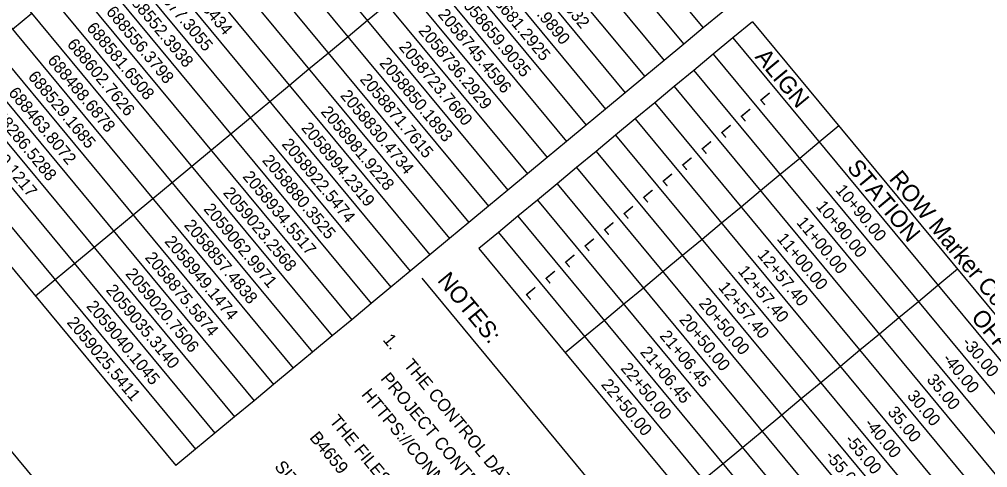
# Model space of a CAD drawing. Extents: x 2057130 to 2060012, y 687175 to 689912.
# Drawn here: x 2058231 to 2058941, y 687802 to 688130 of the extents above; entities that cross this region are included whole.
import ezdxf

# ---------------------------------------------------------------- set-up
doc = ezdxf.new("R2010")
doc.units = 0
for name, color, linetype in [('CTL Sheet Border CELL', 7, 'Continuous'), ('CTL Sheet Notes CELL', 7, 'Continuous'), ('CTL Sheet Table Cell', 7, 'Continuous'), ('CTL Sheet Text', 7, 'Continuous')]:
    doc.layers.add(name, color=color, linetype=linetype)

msp = doc.modelspace()

# ---------------------------------------------------------------- linework, layer by layer
at = {"layer": 'CTL Sheet Border CELL'}
msp.add_lwpolyline([(2059967.32, 688179.94), (2058531.08, 689911.91), (2057318.71, 688906.55), (2058754.95, 687174.58)], close=True, dxfattribs=at)
at = {"layer": 'CTL Sheet Notes CELL'}
msp.add_line((2058526.13, 687940.24), (2058938.91, 687442.47), dxfattribs=at)
at = {"layer": 'CTL Sheet Table Cell'}
for p, q in [((2058289.23, 688658.24), (2058732.52, 688123.68)), ((2058274.91, 688646.37), (2058718.2, 688111.81)), ((2058260.59, 688634.5), (2058703.88, 688099.93)), ((2058246.27, 688622.62), (2058689.56, 688088.06)), ((2058231.95, 688610.75), (2058675.24, 688076.18)), ((2058217.63, 688598.87), (2058660.92, 688064.31)), ((2058203.32, 688587), (2058646.6, 688052.44)), ((2058189, 688575.13), (2058632.28, 688040.56)), ((2058174.68, 688563.25), (2058617.97, 688028.69)), ((2058160.36, 688551.38), (2058603.65, 688016.81)), ((2058146.04, 688539.51), (2058589.33, 688004.94)), ((2058131.72, 688527.63), (2058575.01, 687993.07)), ((2058117.4, 688515.76), (2058560.69, 687981.19)), ((2058103.08, 688503.88), (2058546.37, 687969.32)), ((2058088.77, 688492.01), (2058532.05, 687957.45)), ((2058074.45, 688480.14), (2058517.73, 687945.57)), ((2058060.13, 688468.26), (2058503.42, 687933.7)), ((2058045.81, 688456.39), (2058489.1, 687921.82)), ((2058031.49, 688444.52), (2058474.78, 687909.95)), ((2058031.49, 688444.52), (2058474.78, 687909.95)), ((2058017.17, 688432.64), (2058460.46, 687898.08)), ((2058002.85, 688420.77), (2058446.14, 687886.2)), ((2057988.54, 688408.89), (2058431.82, 687874.33)), ((2057974.22, 688397.02), (2058417.5, 687862.46)), ((2057959.9, 688385.15), (2058403.19, 687850.58)), ((2057945.58, 688373.27), (2058388.87, 687838.71)), ((2057931.26, 688361.4), (2058374.55, 687826.83)), ((2057916.94, 688349.53), (2058360.23, 687814.96)), ((2057902.62, 688337.65), (2058345.91, 687803.09)), ((2058500.74, 688140.91), (2058486.42, 688129.04)), ((2058240.33, 688134.39), (2058226.01, 688122.52)), ((2058746.83, 688135.55), (2058732.52, 688123.68)), ((2058486.42, 688129.04), (2058472.1, 688117.16)), ((2058732.52, 688123.68), (2058718.2, 688111.81)), ((2058768.52, 688128.23), (2058754.2, 688116.36)), ((2058768.52, 688128.23), (2059211.81, 687593.67)), ((2058472.1, 688117.16), (2058457.78, 688105.29)), ((2058754.2, 688116.36), (2058739.88, 688104.49)), ((2058754.2, 688116.36), (2059197.49, 687581.8)), ((2058718.2, 688111.81), (2058703.88, 688099.93)), ((2058457.78, 688105.29), (2058443.47, 688093.42)), ((2058739.88, 688104.49), (2058725.56, 688092.61)), ((2058739.88, 688104.49), (2059183.17, 687569.92)), ((2058703.88, 688099.93), (2058689.56, 688088.06)), ((2058443.47, 688093.42), (2058429.15, 688081.54)), ((2058689.56, 688088.06), (2058675.24, 688076.18)), ((2058725.56, 688092.61), (2058711.24, 688080.74)), ((2058725.56, 688092.61), (2059168.85, 687558.05)), ((2058429.15, 688081.54), (2058414.83, 688069.67)), ((2058711.24, 688080.74), (2058696.92, 688068.87)), ((2058711.24, 688080.74), (2059154.53, 687546.17)), ((2058675.24, 688076.18), (2058660.92, 688064.31)), ((2058414.83, 688069.67), (2058400.51, 688057.79)), ((2058696.92, 688068.87), (2058682.61, 688056.99)), ((2058696.92, 688068.87), (2059140.21, 687534.3)), ((2058660.92, 688064.31), (2058646.6, 688052.44)), ((2058400.51, 688057.79), (2058386.19, 688045.92)), ((2058646.6, 688052.44), (2058632.28, 688040.56)), ((2058682.61, 688056.99), (2058668.29, 688045.12)), ((2058682.61, 688056.99), (2059125.89, 687522.43)), ((2058386.19, 688045.92), (2058371.87, 688034.05)), ((2058668.29, 688045.12), (2058653.97, 688033.24)), ((2058668.29, 688045.12), (2059111.57, 687510.55)), ((2058831.84, 688051.87), (2058817.53, 688039.99)), ((2058632.28, 688040.56), (2058617.97, 688028.69)), ((2058817.53, 688039.99), (2058803.21, 688028.12)), ((2058371.87, 688034.05), (2058357.55, 688022.17)), ((2058653.97, 688033.24), (2058639.65, 688021.37)), ((2058653.97, 688033.24), (2059097.26, 687498.68)), ((2058617.97, 688028.69), (2058603.65, 688016.81)), ((2058803.21, 688028.12), (2058788.89, 688016.25)), ((2058357.55, 688022.17), (2058343.24, 688010.3)), ((2058603.65, 688016.81), (2058589.33, 688004.94)), ((2058639.65, 688021.37), (2058625.33, 688009.5)), ((2058639.65, 688021.37), (2059082.94, 687486.81)), ((2058343.24, 688010.3), (2058328.92, 687998.42)), ((2058788.89, 688016.25), (2058774.57, 688004.37)), ((2058589.33, 688004.94), (2058575.01, 687993.07)), ((2058625.33, 688009.5), (2058611.01, 687997.62)), ((2058625.33, 688009.5), (2059068.62, 687474.93)), ((2058774.57, 688004.37), (2058760.25, 687992.5)), ((2058328.92, 687998.42), (2058314.6, 687986.55)), ((2058611.01, 687997.62), (2058596.69, 687985.75)), ((2058611.01, 687997.62), (2059054.3, 687463.06)), ((2058575.01, 687993.07), (2058560.69, 687981.19)), ((2058760.25, 687992.5), (2058745.93, 687980.62)), ((2058314.6, 687986.55), (2058300.28, 687974.68)), ((2058560.69, 687981.19), (2058546.37, 687969.32)), ((2058596.69, 687985.75), (2058582.37, 687973.87)), ((2058596.69, 687985.75), (2059039.98, 687451.18)), ((2058300.28, 687974.68), (2058285.96, 687962.8)), ((2058745.93, 687980.62), (2058731.61, 687968.75)), ((2058546.37, 687969.32), (2058532.05, 687957.45)), ((2058582.37, 687973.87), (2058568.06, 687962)), ((2058582.37, 687973.87), (2059025.66, 687439.31)), ((2058731.61, 687968.75), (2058717.29, 687956.88)), ((2058285.96, 687962.8), (2058271.64, 687950.93)), ((2058568.06, 687962), (2059011.34, 687427.44)), ((2058532.05, 687957.45), (2058517.73, 687945.57)), ((2058717.29, 687956.88), (2058702.98, 687945)), ((2058271.64, 687950.93), (2058257.32, 687939.06)), ((2058918.92, 687946.86), (2058904.6, 687934.99)), ((2058257.32, 687939.06), (2058243, 687927.18)), ((2058517.73, 687945.57), (2058503.42, 687933.7)), ((2058702.98, 687945), (2058688.66, 687933.13)), ((2058503.42, 687933.7), (2058489.1, 687921.82)), ((2058688.66, 687933.13), (2058674.34, 687921.26)), ((2058904.6, 687934.99), (2058890.28, 687923.12)), ((2058489.1, 687921.82), (2058474.78, 687909.95)), ((2058674.34, 687921.26), (2058660.02, 687909.38)), ((2058890.28, 687923.12), (2058875.96, 687911.24)), ((2058875.96, 687911.24), (2058861.64, 687899.37)), ((2058474.78, 687909.95), (2058460.46, 687898.08)), ((2058660.02, 687909.38), (2058645.7, 687897.51)), ((2058460.46, 687898.08), (2058446.14, 687886.2)), ((2058645.7, 687897.51), (2058631.38, 687885.63)), ((2058861.64, 687899.37), (2058847.33, 687887.49)), ((2058446.14, 687886.2), (2058431.82, 687874.33)), ((2058847.33, 687887.49), (2058833.01, 687875.62)), ((2058833.01, 687875.62), (2058818.69, 687863.75)), ((2058431.82, 687874.33), (2058417.5, 687862.46)), ((2058417.5, 687862.46), (2058403.19, 687850.58)), ((2058818.69, 687863.75), (2058804.37, 687851.87)), ((2058403.19, 687850.58), (2058388.87, 687838.71)), ((2058804.37, 687851.87), (2058790.05, 687840)), ((2058790.05, 687840), (2058775.73, 687828.13)), ((2058388.87, 687838.71), (2058374.55, 687826.83)), ((2058374.55, 687826.83), (2058360.23, 687814.96)), ((2058775.73, 687828.13), (2058761.41, 687816.25)), ((2058360.23, 687814.96), (2058345.91, 687803.09)), ((2058761.41, 687816.25), (2058747.09, 687804.38)), ((2058747.09, 687804.38), (2058732.78, 687792.5))]:
    msp.add_line(p, q, dxfattribs=at)

# ---------------------------------------------------------------- texts
at = {"layer": 'CTL Sheet Notes CELL'}
for s, height, rotation, p in [('ALIGN', 12.401, 309.66721, (2058769.92, 688102.25)), ('STATION', 12.401, 309.66721, (2058837.27, 688021.04)), ('ROW Marker Concrete or Granite-E', 12.4009, 309.66721, (2058868.2, 688012.88)), ('NOTES:', 12.26, 309.56196, (2058537.09, 687938.48)), ('OFFSET', 12.401, 309.66721, (2058928.27, 687911.3)), ('1.    THE CONTROL DATA FOR THIS PROJECT CAN BE FOUND ELECTRONICALLY BY SELECTING', 9.1951, 309.66721, (2058497.15, 687894.97)), ('PROJECT CONTROL DATA AT:', 9.1951, 309.66721, (2058495.48, 687866.52)), ('HTTPS://CONNECT.NCDOT.GOV/RESOURCES/LOCATION/PAGES', 9.1951, 309.66721, (2058481.44, 687854.88)), ('THE FILES TO BE FOUND ARE AS FOLLOWS:', 9.1951, 309.66721, (2058458.05, 687835.49)), ('B4659_LS_CONTROL.TXT', 9.1951, 309.66721, (2058443.35, 687823.3)), ('SITE CALIBRATION INFORMATION HAS NOT BEEN PROVIDED FOR THIS PROJECT. IF FURTHER', 9.1951, 309.66721, (2058417.66, 687801.99))]:
    msp.add_text(s, height=height, rotation=rotation, dxfattribs=at).set_placement(p)
at = {"layer": 'CTL Sheet Text'}
for s, height, p in [('2058587.4932', 8.8578, (2058594.81, 688180.8)), ('688715.3434', 8.8578, (2058337.21, 688170.9)), ('2058597.9890', 8.8578, (2058580.5, 688168.93)), ('688577.3055', 8.8578, (2058322.89, 688159.03)), ('2058681.2925', 8.8578, (2058566.18, 688157.05)), ('688552.3938', 8.8578, (2058308.57, 688147.16)), ('2058659.9035', 8.8578, (2058551.86, 688145.18)), ('688556.3798', 8.8578, (2058294.25, 688135.28)), ('2058745.4596', 8.8578, (2058537.54, 688133.31)), ('688581.6508', 8.8578, (2058279.93, 688123.41)), ('2058736.2929', 8.8578, (2058523.22, 688121.43)), ('688602.7626', 8.8578, (2058265.61, 688111.53)), ('2058723.7660', 8.8578, (2058508.9, 688109.56)), ('688488.6878', 8.8578, (2058251.3, 688099.66)), ('2058850.1893', 8.8578, (2058494.58, 688097.69)), ('688529.1685', 8.8578, (2058236.98, 688087.79)), ('2058871.7615', 8.8578, (2058480.27, 688085.81)), ('688463.8072', 8.8578, (2058222.66, 688075.91)), ('2058830.4734', 8.8578, (2058465.95, 688073.94)), ('L', 8.86, (2058773.42, 688071.67)), ('688286.5288', 8.8578, (2058208.34, 688064.04)), ('2058981.9228', 8.8578, (2058451.63, 688062.06)), ('L', 8.86, (2058759.11, 688059.79)), ('688290.1217', 8.8578, (2058194.02, 688052.17)), ('2058994.2319', 8.8578, (2058437.31, 688050.19)), ('L', 8.86, (2058744.79, 688047.92)), ('2058922.5474', 8.8578, (2058422.99, 688038.32)), ('L', 8.86, (2058730.47, 688036.05)), ('2058880.3525', 8.8578, (2058408.67, 688026.44)), ('L', 8.86, (2058716.15, 688024.17)), ('2058934.5517', 8.8578, (2058394.35, 688014.57)), ('L', 8.86, (2058701.83, 688012.3)), ('2059023.2568', 8.8578, (2058380.03, 688002.7)), ('L', 8.86, (2058687.51, 688000.43)), ('10+90.00', 8.858, (2058828.99, 688004.66)), ('10+90.00', 8.858, (2058814.67, 687992.79)), ('2059062.9971', 8.8578, (2058365.72, 687990.82)), ('L', 8.86, (2058673.19, 687988.55)), ('2058857.4838', 8.8578, (2058351.4, 687978.95)), ('L', 8.86, (2058658.87, 687976.68)), ('11+00.00', 8.858, (2058800.35, 687980.91)), ('2058949.1474', 8.8578, (2058337.08, 687967.07)), ('L', 8.86, (2058644.56, 687964.8)), ('11+00.00', 8.858, (2058786.03, 687969.04)), ('12+57.40', 8.858, (2058771.72, 687957.16)), ('2058875.5874', 8.8578, (2058322.76, 687955.2)), ('L', 8.86, (2058630.24, 687952.93)), ('2059020.7506', 8.8578, (2058308.44, 687943.33)), ('L', 8.86, (2058615.92, 687941.06)), ('12+57.40', 8.858, (2058757.4, 687945.29)), ('2059035.3140', 8.8578, (2058294.12, 687931.45)), ('L', 8.86, (2058601.6, 687929.18)), ('12+57.40', 8.858, (2058743.08, 687933.42)), ('20+50.00', 8.858, (2058728.76, 687921.54)), ('2059040.1045', 8.8578, (2058279.8, 687919.58)), ('2059025.5411', 8.8578, (2058265.48, 687907.71)), ('20+50.00', 8.858, (2058714.44, 687909.67)), ('21+06.45', 8.858, (2058700.12, 687897.8)), ('21+06.45', 8.858, (2058685.8, 687885.92)), ('-30.00', 8.858, (2058921.67, 687892.89)), ('-40.00', 8.858, (2058907.36, 687881.02)), ('22+50.00', 8.858, (2058671.49, 687874.05)), ('35.00', 8.858, (2058895.84, 687865.76)), ('22+50.00', 8.858, (2058657.17, 687862.17)), ('30.00', 8.858, (2058881.52, 687853.89)), ('35.00', 8.858, (2058867.2, 687842.01)), ('-40.00', 8.858, (2058850.08, 687833.52)), ('-55.00', 8.858, (2058835.76, 687821.65)), ('-55.00', 8.858, (2058821.44, 687809.77))]:
    msp.add_text(s, height=height, rotation=309.66721, dxfattribs=at).set_placement(p)

doc.saveas('drawing.dxf')
